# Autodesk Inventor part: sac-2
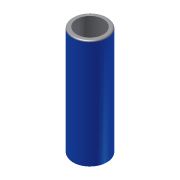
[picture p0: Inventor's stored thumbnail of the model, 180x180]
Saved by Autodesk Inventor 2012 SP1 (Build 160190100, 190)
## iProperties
Created: 2014-08
Part Number: sac-2
Material: Default
Document SubType Name: Modeling
Designer: Bruno
Density: 1 g/cm^3
Author: Bruno
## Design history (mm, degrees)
sketch "Esquisse1"
  geometry: C1 r 135 at (0, 0); 1 further point
  constraints: 1 centre point, 1 coincident
  dimensions: "d0" = 270 diameter of C1
extrude "Extrusion1" new body sketch "Esquisse1" distance "d1" = 860; taper "d2" = 0 deg
fillet "Congé1" dims "d3" = 10
sketch "Esquisse2"
  geometry: C1 r 125 at (0, 0) reference; C2 r 104.385 at (0, 0)
  constraints: 1 centre point, 1 coincident
extrude "Extrusion4" cut sketch "Esquisse2" distance "d11" = 830; taper "d12" = 0 deg
node "Solide1"
